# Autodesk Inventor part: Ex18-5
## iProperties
Author: Elise Moss
Revision Number: A
Created: 2001-09
Part Number: Ex18-5
Description: BALL, HANDLE
Document SubType Name: Modeling
Designer: Elise Moss
Control State: 0
Master: False
Checked Out: False
PropertySet Name: Design Tracking Control
Length Units: 11272
Angle Units: 11279
Time Units: 11290
Mass Units: 11286
Shininess: 3
Angle Display Precision: 2
Document Length Units: 11272
Document Angle Units: 11286
Document Time Units: 11279
Document Mass Units: 11290
Document Length Units Precision: 3
Document Angle Units Precision: 0
Compacted: False
PropertySet Name: _Private Model Information
Density: 0.0
Volumn: 0.0
Area: 0.0
PropertySet Name: Model Information
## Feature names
1. Revolution1
